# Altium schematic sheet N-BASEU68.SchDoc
size A4; DocumentNumber: 1; SheetNumber: 1; SheetTotal: 1; PageSetup: Record=PageOptions¦CenterHorizontal=True¦CenterVertical=True¦PrintScale=0.05¦XCorrection=1.00¦YCorrection=1.00¦PrintKind=0¦BorderSize=5000000¦LeftOffset=0¦BottomOffset=0¦Orientation=2¦PaperLength=1000¦PaperWidth=1000¦Scale=100¦PaperSource=7¦PrintQuality=-3¦MediaType=1¦DitherType=10¦PrintScaleMode=1¦PaperKind=12mm¦PaperIndex=126
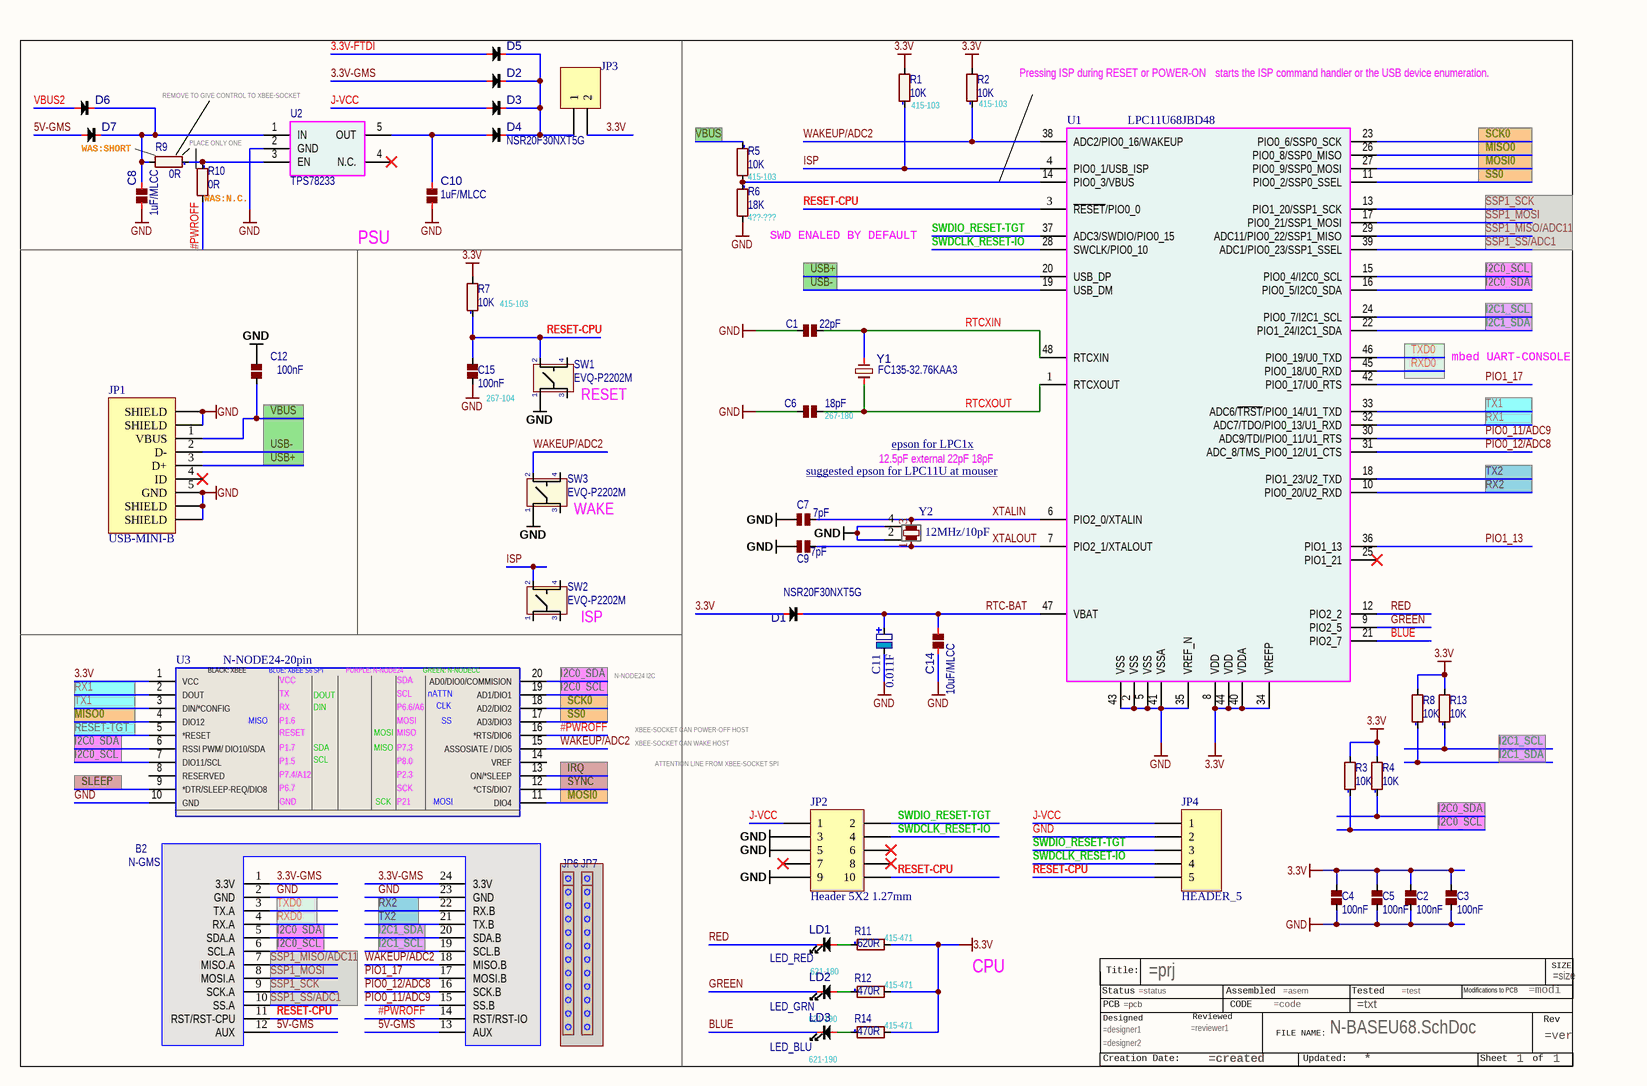
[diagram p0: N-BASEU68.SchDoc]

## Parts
?*??  FILE_NAME: N-BASEU68.SchDoc  PAGE NUMPER: 1  (hidden comment: TITLEBLOCK3)  (graphical)
B2  N-GMS  [N-GMS]
C1  22pF  [0603_cap]
C2  100nF  [0603_cap]
C3  100nF  [0603_cap]
C4  100nF  [0603_cap]
C5  100nF  [0603_cap]
C6  18pF  CODE: 267-180  [0603_cap]
C7  7pF  [0603_cap]
C8  1uF/MLCC  [0603_CAP]
C9  7pF  [0603_cap]
C10  1uF/MLCC  [0603_CAP]
C11  0.011F  [SUPERCAP  PAS3225P3R3113]
C12  100nF  [0603_cap]
C14  10uF/MLCC  [0603_CAP]
C15  100nF  CODE: 267-104  [0603_cap]
D1  NSR20F30NXT5G  [0603_DIODE-CASE_152AB]
D2  NSR20F30NXT5G  [0603_DIODE-CDSU101A]  (value not drawn)
D3  NSR20F30NXT5G  [0603_DIODE-CDSU101A]  (value not drawn)
D4  NSR20F30NXT5G  [0603_DIODE-CDSU101A]
D5  NSR20F30NXT5G  [0603_DIODE-CDSU101A]  (value not drawn)
D6  NSR20F30NXT5G  [0603_DIODE-CDSU101A]  (value not drawn)
D7  NSR20F30NXT5G  [0603_DIODE-CDSU101A]  (value not drawn)
JP1  USB-MINI-B  [USB-MINI-B-HIR-UX60A-MB-5ST]
JP2  Header 5X2 1.27mm  [2x5-1.27mm-HARWIN-855-M50-3600542]
JP3  HEADER-2  [1X02]  (value not drawn)
JP4  HEADER_5  [1X05]
JP6  HEADER 9  [1X12-NOSILK]  (value not drawn)  (masked out: inside a compile mask, not in the netlist)
JP7  HEADER 9  [1X12-NOSILK]  (value not drawn)  (masked out: inside a compile mask, not in the netlist)
LD1  LED_RED  CODE: 621-180  [0603_LED_RED]
LD2  LED_GRN  CODE: 621-190  [0603_LED_GRN]
LD3  LED_BLU  CODE: 621-190  [0603_LED_BLU]
R1  10K  CODE: 415-103  [0603_res]
R2  10K  CODE: 415-103  [0603_res]
R3  10K  [0603_res]
R4  10K  [0603_res]
R5  10K  CODE: 415-103  [0603_res]
R6  18K  CODE: 4??-???  [0603_res]
R7  10K  CODE: 415-103  [0603_res]
R8  10K  [0603_res]
R9  0R  [0603_res]
R10  0R  [0603_res]
R11  620R  CODE: 415-471  [0603_res]
R12  470R  CODE: 415-471  [0603_res]
R13  10K  [0603_res]
R14  470R  CODE: 415-471  [0603_res]
SW1  EVQ-P2202M  [BUTTON_4.7x3.5mm]
SW2  EVQ-P2202M  [BUTTON_4.7x3.5mm]
SW3  EVQ-P2202M  [BUTTON_4.7x3.5mm]
U1  LPC11U68JBD48  [SOT313-2_V]
U2  TPS78233  [SOT23-5_0.95mm-NOSILK]
U3  N-NODE24-20pin  [N-NODE24-20pins]
Y1  FC135-32.76KAA3  [CRYSTAL-3.2x1.5]
Y2  12MHz/10pF  [CRY-SMD4-EPSON-FA238V]

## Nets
3.3V: C2.1 C3.1 C4.1 C5.1 D1.1 JP3.2 R1.2 R2.2 R3.2 R4.2 R7.2 R8.2 R11.2 R12.2 R13.2 R14.2 U1.8(VDD) U1.34(VREFP) U1.40(VDDA) U1.44(VDD) U3.1(VCC)
GND: B2.2(GND) B2.23(GND) C1.2 C2.2 C3.2 C4.2 C5.2 C6.2 C7.2 C8.1 C9.2 C10.1 C11.2 C12.1 C14.1 C15.2 JP1.5(GND) JP1.6(SHIELD) JP1.7(SHIELD) JP1.8(SHIELD) JP1.9(SHIELD) JP2.3 JP2.5 JP2.9 JP4.2 R6.2 SW1.1 SW3.1 U1.2(VSS) U1.5(VSS) U1.35(VREF_N) U1.41(VSSA) U1.43(VSS) U2.2(GND) U3.10(GND) Y2.2 Y2.4
3.3V-FTDI: D5.1
3.3V-GMS: B2.1(3.3V) B2.24(3.3V) D2.1
5V-GMS: B2.12(AUX) B2.13(AUX) D7.1
#PWROFF: B2.14(RST/RST-IO) R10.2 U3.16(*RTS/DIO6)
BLUE: LD3.2 U1.21(PIO2_7)
GREEN: LD2.2 U1.9(PIO2_5)
I2C0_SCL: B2.6(SCL.A) R3.1 U1.15(PIO0_4/I2C0_SCL) U3.7(DIO11/SCL) U3.19(AD1/DIO1)
I2C0_SDA: B2.5(SDA.A) R4.1 U1.16(PIO0_5/I2C0_SDA) U3.6(RSSI_PWM/_DIO10/SDA) U3.20(AD0/DIO0/COMMISION)
I2C1_SCL: B2.19(SCL.B) R13.1 U1.24(PIO0_7/I2C1_SCL)
I2C1_SDA: B2.20(SDA.B) R8.1 U1.22(PIO1_24/I2C1_SDA)
IRQ: U3.13(ON/*SLEEP)
ISP: R1.1 SW2.2 U1.4(PIO0_1/USB_ISP)
J-VCC: D3.1 JP2.1 JP4.1
MISO0: U1.26(PIO0_8/SSP0_MISO) U3.4(DIO12)
MOSI0: U1.27(PIO0_9/SSP0_MOSI) U3.11(DIO4)
PIO0_11/ADC9: B2.15(SS.B) U1.30(ADC9/TDI/PIO0_11/U1_RTS)
PIO0_12/ADC8: B2.16(SCK.B) U1.31(ADC_8/TMS_PIO0_12/U1_CTS)
PIO1_13: U1.36(PIO1_13)
PIO1_17: B2.17(MOSI.B) U1.42(PIO0_17/U0_RTS)
RED: LD1.2 U1.12(PIO2_2)
RESET-CPU: B2.11(RST/RST-CPU) C15.1 JP2.10 JP4.5 R7.1 SW1.2 U1.3(~{RESET}/PIO0_0)
RESET-TGT: U3.5(*RESET)
RTC-BAT: C11.1 C14.2 D1.2 U1.47(VBAT)
RTCXIN: C1.1 U1.48(RTCXIN) Y1.1
RTCXOUT: C6.1 U1.1(RTCXOUT) Y1.2
RX1: U1.32(ADC7/TDO/PIO0_13/U1_RXD) U3.2(DOUT)
RX2: B2.22(RX.B) U1.10(PIO0_20/U2_RXD)
RXD0: B2.4(RX.A) U1.45(PIO0_18/U0_RXD)
SCK0: U1.23(PIO0_6/SSP0_SCK) U3.18(AD2/DIO2)
SLEEP: U3.9(*DTR/SLEEP-REQ/DIO8)
SS0: U1.11(PIO0_2/SSP0_SSEL) U3.17(AD3/DIO3)
SSP1_MISO/ADC11: B2.7(MISO.A) U1.29(ADC11/PIO0_22/SSP1_MISO)
SSP1_MOSI: B2.8(MOSI.A) U1.17(PIO0_21/SSP1_MOSI)
SSP1_SCK: B2.9(SCK.A) U1.13(PIO1_20/SSP1_SCK)
SSP1_SS/ADC1: B2.10(SS.A) U1.39(ADC1/PIO0_23/SSP1_SSEL)
SWDCLK_RESET-IO: JP2.4 JP4.4 U1.28(SWCLK/PIO0_10)
SWDIO_RESET-TGT: JP2.2 JP4.3 U1.37(ADC3/SWDIO/PIO0_15)
SYNC: U3.12(*CTS/DIO7)
TX1: U1.33(ADC6/~{TRST}/PIO0_14/U1_TXD) U3.3(DIN/*CONFIG)
TX2: B2.21(TX.B) U1.18(PIO1_23/U2_TXD)
TXD0: B2.3(TX.A) U1.46(PIO0_19/U0_TXD)
USB+: JP1.3(D+) U1.20(USB_DP)
USB-: JP1.2(D-) U1.19(USB_DM)
VBUS: C12.2 JP1.1(VBUS) R5.1
VBUS2: D6.1
WAKEUP/ADC2: B2.18(MISO.B) R2.1 SW3.2 U1.38(ADC2/PIO0_16/WAKEUP) U3.15(ASSOSIATE_/_DIO5)
XTALIN: C7.1 U1.6(PIO2_0/XTALIN) Y2.3
XTALOUT: C9.1 U1.7(PIO2_1/XTALOUT) Y2.1
NetC8_2: C8.2 D6.2 D7.2 R9.2 U2.1(IN)
NetC10_2: C10.2 D4.1 U2.5(OUT)
NetD2_2: D2.2 D3.2 D4.2 D5.2 JP3.1
NetLD1_1: LD1.1 R11.1
NetLD2_1: LD2.1 R12.1
NetLD3_1: LD3.1 R14.1
NetR5_2: R5.2 R6.1 U1.14(PIO0_3/VBUS)
NetR9_1: R9.1 R10.1 U2.3(EN)

Not connected (* = marked no-connect by the designer): ?*?? ?1; JP1 4(ID)*; JP2 6* 7* 8*; SW1 3 4; SW2 1 3 4; SW3 3 4; U1 25(PIO1_21)*; U2 4(N.C.)*; U3 8(RESERVED) 14(VREF)

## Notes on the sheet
- Pressing ISP during RESET or POWER-ON
- starts the ISP command handler or the USB device enumeration.
- (near D7) WAS:SHORT
- (near U2) REMOVE TO GIVE CONTROL TO XBEE-SOCKET
- PLACE ONLY ONE
- (near R10) WAS:N.C.
- PSU
- (near R6) SWD ENALED BY DEFAULT
- (near SW1) RESET
- mbed UART-CONSOLE
- suggested epson for LPC11U at mouser <http://www.mouser.ie/ProductDetail/Epson-Timing/FC-135-327680KA-A3/?qs=sGAEpiMZZMsBj6bBr9Q9aZLqXgWtLYAXgtkp1R7gwzo%3d>
- (near U1) 12.5pF external 22pF 18pF
- epson for LPC1x <http://www5.epsondevice.com/en/quartz/tech/c_design/nxp/lpc1x.html>
- (near SW3) WAKE
- (near SW2) ISP
- N-NODE24 I2C
- XBEE-SOCKET CAN WAKE HOST
- XBEE-SOCKET CAN POWER-OFF HOST
- ATTENTION LINE FROM XBEE-SOCKET SPI
- CPU

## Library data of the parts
B2 = N-GMS: Divider: 1
C1 C7 C9 = C: CAPACITOR; Divider: 1; S.Description: Multilayer Ceramic Capacitors MLCC - SMD/SMT 0603 22pF 50volts C0G 5%
C2-C5 C12 = C: CAPACITOR; S.Description: Multilayer Ceramic Capacitors MLCC - SMD/SMT 50volts 0.1uF 10% X7R; Divider: 1
C6 = C: CAPACITOR; Divider: 1; S.Description: Multilayer Ceramic Capacitors MLCC - SMD/SMT 0402 18pF 25volts C0G 5%
C8 C10 = C: CAPACITOR; Divider: 1; S.Description: Multilayer Ceramic Capacitors MLCC - SMD/SMT 0603 1.0uF 16volts X7R 10%
C11 = CP_SUPERCAP: Divider: 1; S.Description: Supercapacitors / Ultracapacitors SUPER CAP 3.3V 0.011F
C14 = C: CAPACITOR; S.Description: Multilayer Ceramic Capacitors MLCC - SMD/SMT 10UF 6.3V 20% 0402; Divider: 1
C15 = C: CAPACITOR; Divider: 1; S.Description: Multilayer Ceramic Capacitors MLCC - SMD/SMT 0402 0.1uF 16volts X7R 10%
D1 = DIODE: Divider: 1; S.Description: Schottky Diodes & Rectifiers 0603 FC SCHOTTKY DIODES
D2-D7 = DIODE: CODE: 605-020; S.Description: Schottky Diodes & Rectifiers 0603 FC SCHOTTKY DIODES; Divider: 1
JP1 = USB-MINI-B: S.Description: USB Connectors MINI B RECEPT RA SMT W/O POST; Divider: 1
JP2 = Header 5X2: Header, 5-Pin, Dual row; S.Description: Headers & Wire Housings 5+5 DIL PIN HDR SMT Au/Sn; Divider: 1
JP3 = HEADER-2: Divider: 1
JP4 = HEADER_5: Divider: 1
JP6 JP7 = HDR12: Divider: 0.25; S.Description: Headers & Wire Housings 50P SINGLE ROW
LD1 = LED: Divider: 1; S.Description: Standard LEDs - SMD 0402 SUPER RED Non-Diff
LD2 LD3 = LED: Divider: 1; S.Description: Standard LEDs - SMD 0402 GREEN Non-Diff
R1 R2 R5 R7 = R: RESISTOR; Divider: 1; S.Description: Thick Film Resistors - SMD 1/16watt 10Kohms 1%
R3 R4 R8 R13 = R: RESISTOR; S.Description: Thick Film Resistors - SMD 0603 10Kohms 1% Tol; Divider: 1
R6 = R: RESISTOR; Divider: 1; S.Description: Thick Film Resistors - SMD 1/16watt 18.2Kohms 1%
R9 R10 = R: RESISTOR; Divider: 1; S.Description: Thick Film Resistors - SMD 0603 Zero Ohms
R11 = R: RESISTOR; Divider: 1; S.Description: Thick Film Resistors - SMD 1/16watt 680ohms 1%
R12 R14 = R: RESISTOR; Divider: 1; S.Description: Thick Film Resistors - SMD 1/16watt 470ohms 1% 100ppm
SW1-SW3 = BUTTON_TACT: BUTTON TACTILE; S.Description: Tactile Switches 4.7x3.5mm SMD Light Touch Switch; Divider: 1
U1 = LPC11U68JBD48_1: Divider: 1; S.Description: NXP - LPC11U68JBD48E - MCU, 32BIT, CORTEX-M0+, 50MHZ, LQFP-48
U2 = NCP702N: S.Description: LDO Voltage Regulators Sgl Fixed Out LDO 150mA,1uA Quies Crnt; Divider: 1
U3 = N-NODE24-20pin: Divider: 1
Y1 = XTAL: CRYSTAL; Divider: 1; S.Description: Crystals 32.768KHz 20ppm 12.5pF -40C -85C
Y2 = XTAL_4PINS: CRYSTAL; S.Description: ABRACON - ABM8G-12.000MHZ-B4Y-T - CRYSTAL, 12MHZ, 18PF, SMD; Divider: 1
